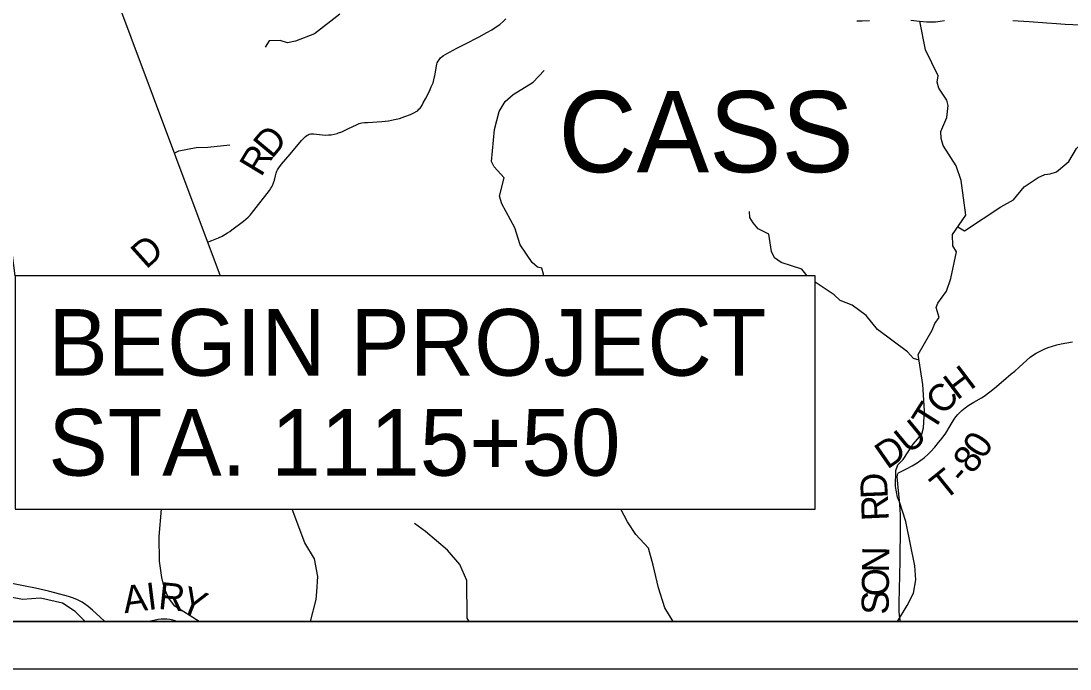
# Model space of a CAD drawing. Extents: x 0 to 34, y 0 to 22.
# Drawn here: x 26.74 to 28.944, y 14 to 15.361 of the extents above; entities that cross this region are included whole.
import ezdxf

# ---------------------------------------------------------------- set-up
doc = ezdxf.new("R2010")
doc.units = 0
for name, color, linetype in [('GM_X_Adjacent_County', 7, 'Continuous'), ('GM_X_County', 7, 'Continuous'), ('GM_X_Minor_River', 7, 'Continuous'), ('GM_X_Township', 7, 'Continuous'), ('GM_X_Township_Road', 7, 'Continuous'), ('GM_X_Township_Road_Text', 7, 'Continuous'), ('GM_X_Township_Text', 7, 'Continuous'), ('SH_Data', 7, 'Continuous'), ('SH_Text', 7, 'Continuous')]:
    doc.layers.add(name, color=color, linetype=linetype)

msp = doc.modelspace()

# ---------------------------------------------------------------- linework, layer by layer
at = {"layer": 'GM_X_Adjacent_County'}
msp.add_lwpolyline([(24.0167, 18.0693), (24.0167, 14.1), (30.8167, 14.1), (30.8167, 17.8174)], dxfattribs=at)
at = {"layer": 'GM_X_County'}
msp.add_lwpolyline([(24.0167, 18.0693), (24.0167, 14.1), (30.8167, 14.1), (30.8167, 17.8174)], dxfattribs=at)
at = {"layer": 'GM_X_Minor_River'}
for points in [[(27.4101, 15.3755), (27.3568, 15.3343), (27.3167, 15.3186), (27.2997, 15.3151), (27.2845, 15.3203), (27.2614, 15.3194), (27.2527, 15.3061)], [(28.582, 14.1), (28.6017, 14.1332), (28.6156, 14.1595), (28.62, 14.1876), (28.618, 14.2164), (28.5993, 14.3096), (28.5859, 14.3509), (28.5817, 14.3608), (28.5774, 14.3835), (28.5784, 14.4173), (28.5821, 14.4287), (28.5938, 14.4401), (28.6149, 14.4725), (28.6326, 14.4934), (28.636, 14.5063), (28.6381, 14.5424), (28.6352, 14.5974), (28.6254, 14.6603), (28.6547, 14.7117), (28.66, 14.7257), (28.6694, 14.7387), (28.6628, 14.7591), (28.6662, 14.7686), (28.6843, 14.7934), (28.694, 14.8203), (28.7059, 14.8765), (28.6982, 14.8886), (28.6974, 14.9129), (28.7249, 14.9536), (28.7154, 15.0264), (28.705, 15.0567), (28.6776, 15.0995), (28.6737, 15.1143), (28.6725, 15.1287), (28.6852, 15.1587), (28.6878, 15.1834), (28.6851, 15.1947), (28.6683, 15.2201), (28.6652, 15.233), (28.6674, 15.2463), (28.6406, 15.3004), (28.6286, 15.3606)], [(28.7082, 14.929), (28.7227, 14.9202), (28.7987, 14.9707), (28.8251, 14.9852), (28.8481, 15.013), (28.8769, 15.0325), (28.8912, 15.039), (28.9026, 15.0402), (28.9155, 15.0444), (28.9419, 15.0661), (28.9577, 15.0931), (28.9818, 15.1179), (29.0536, 15.1672), (29.0729, 15.1885), (29.0886, 15.2235), (29.0931, 15.2364), (29.1081, 15.2683), (29.1319, 15.2919), (29.1889, 15.3354), (29.1999, 15.34)], [(27.8381, 14.8261), (27.8382, 14.8297), (27.8347, 14.8418), (27.8249, 14.8444), (27.8142, 14.8538), (27.789, 14.8913), (27.7779, 14.9269), (27.75, 14.9772), (27.7457, 14.9931), (27.7554, 15.0315), (27.7345, 15.0545), (27.7287, 15.0663), (27.7352, 15.1331), (27.7445, 15.1711), (27.7573, 15.192), (27.7743, 15.2068), (27.8159, 15.2328), (27.8393, 15.2572)], [(27.0621, 15.0835), (27.0718, 15.0883), (27.1078, 15.0953), (27.1324, 15.0962), (27.1786, 15.1009)], [(28.3922, 14.8261), (28.3805, 14.8398), (28.3372, 14.8536), (28.3235, 14.8638), (28.3166, 14.8767), (28.3112, 14.9134), (28.2887, 14.9247), (28.2785, 14.9372), (28.2712, 14.9482), (28.2708, 14.9611)], [(28.6271, 14.649), (28.6152, 14.6523), (28.603, 14.6663), (28.5399, 14.713), (28.5155, 14.7429), (28.4862, 14.7644), (28.4611, 14.7738), (28.4489, 14.7862), (28.4085, 14.8128)], [(27.1144, 14.1), (27.0629, 14.1323), (27.0496, 14.1497), (27.0412, 14.169), (27.0361, 14.1921), (27.031, 14.2266), (27.0304, 14.2782), (27.0351, 14.3361)], [(27.3486, 14.1), (27.3604, 14.1461), (27.3618, 14.1624), (27.3636, 14.1943), (27.3566, 14.2311), (27.3364, 14.2651), (27.3095, 14.3361)], [(28.1104, 14.1), (28.0931, 14.1286), (28.0792, 14.1707), (28.068, 14.2184), (28.0584, 14.2541), (28.0321, 14.2828), (28.0146, 14.3092), (28.0002, 14.3361)], [(27.6815, 14.1), (27.6774, 14.1066), (27.6767, 14.1859), (27.6621, 14.2192), (27.6358, 14.2494), (27.5898, 14.2887), (27.567, 14.306)], [(26.8747, 14.1), (26.8538, 14.1207), (26.8275, 14.1381), (26.7809, 14.1485), (26.7434, 14.1461), (26.6959, 14.1553), (26.6838, 14.1587), (26.6424, 14.1718)]]:
    msp.add_lwpolyline(points, dxfattribs=at)
at = {"layer": 'GM_X_Township'}
msp.add_line((26.1244, 14.1), (30.0847, 14.1), dxfattribs=at)
at = {"layer": 'GM_X_Township_Road'}
for points in [[(27.1322, 14.8963), (27.1408, 14.8999), (27.1482, 14.9027), (27.1552, 14.906), (27.1626, 14.9095), (27.168, 14.9124), (27.1742, 14.9161), (27.1786, 14.9192), (27.1829, 14.9227), (27.2075, 14.9408), (27.2124, 14.9447), (27.217, 14.949), (27.2214, 14.9536), (27.2293, 14.9632), (27.2388, 14.9755), (27.2523, 14.9925), (27.2619, 15.0054), (27.2651, 15.0097), (27.267, 15.0126), (27.2688, 15.0158), (27.2709, 15.0211), (27.2724, 15.027), (27.2746, 15.0359), (27.2761, 15.0415), (27.2777, 15.0456), (27.2791, 15.0482), (27.2821, 15.0528), (27.2877, 15.0602), (27.3056, 15.0817), (27.3296, 15.11), (27.3337, 15.1146), (27.3381, 15.1188), (27.3405, 15.1206), (27.3431, 15.1221), (27.3458, 15.1232), (27.3487, 15.1238), (27.3517, 15.124), (27.3547, 15.1239), (27.3733, 15.1219), (27.3795, 15.1216), (27.3858, 15.1217), (27.392, 15.1223), (27.3981, 15.1234), (27.4041, 15.125), (27.4069, 15.1259), (27.4095, 15.1268), (27.4118, 15.1276), (27.4143, 15.1286), (27.4197, 15.131), (27.4281, 15.135), (27.4447, 15.1434), (27.4508, 15.1456), (27.4564, 15.1471), (27.4621, 15.1478), (27.4682, 15.1481), (27.4787, 15.1485), (27.4979, 15.1499), (27.5121, 15.1518), (27.5248, 15.154), (27.5352, 15.1563), (27.5463, 15.1603), (27.5584, 15.1651), (27.5655, 15.1684), (27.5714, 15.1717), (27.5737, 15.1733), (27.5762, 15.1757), (27.5785, 15.1783), (27.5806, 15.1809), (27.5826, 15.1843), (27.5853, 15.1893), (27.5899, 15.1975), (27.5984, 15.2141), (27.6021, 15.2226), (27.6058, 15.2315), (27.6073, 15.2374), (27.6096, 15.2464), (27.6102, 15.2494), (27.613, 15.2669), (27.6138, 15.2702), (27.6146, 15.273), (27.6163, 15.2765), (27.6183, 15.2798), (27.6216, 15.2836), (27.6248, 15.2865), (27.6279, 15.289), (27.6327, 15.2918), (27.656, 15.3038), (27.6642, 15.3083), (27.6724, 15.3127), (27.7028, 15.3282), (27.7191, 15.3368), (27.729, 15.3426), (27.7386, 15.3486), (27.746, 15.3541), (27.7537, 15.3606), (27.7589, 15.3655)], [(28.6099, 15.3631), (28.6279, 15.3607), (28.6433, 15.3594), (28.6533, 15.3594), (28.6617, 15.3595), (28.6713, 15.3606), (28.6807, 15.3621)], [(28.4959, 15.3618), (28.5072, 15.3612), (28.5228, 15.3619)], [(28.8242, 15.3621), (28.858, 15.3604), (28.8956, 15.3575), (28.916, 15.3556), (28.9341, 15.3542), (28.966, 15.3532)], [(28.582, 14.4087), (28.5825, 14.4099), (28.5832, 14.4111), (28.5841, 14.412), (28.585, 14.4128), (28.5877, 14.4144), (28.6017, 14.421), (28.6126, 14.427), (28.6232, 14.4334), (28.631, 14.4385), (28.6384, 14.4441), (28.6454, 14.4503), (28.652, 14.4569), (28.6602, 14.4662), (28.668, 14.4759), (28.6755, 14.4851), (28.6829, 14.4955), (28.6925, 14.511), (28.7007, 14.5246), (28.7043, 14.5297), (28.7081, 14.5345), (28.7123, 14.539), (28.7168, 14.5432), (28.7241, 14.5489), (28.7317, 14.5541), (28.7423, 14.5605), (28.7584, 14.5697), (28.7636, 14.573), (28.776, 14.582), (28.7856, 14.5897), (28.8043, 14.6058), (28.8208, 14.6197), (28.8279, 14.6258), (28.8371, 14.634), (28.8532, 14.6487), (28.8602, 14.6548), (28.8652, 14.6585), (28.8731, 14.6635), (28.8813, 14.6679), (28.8897, 14.6718), (28.8984, 14.6752), (28.9072, 14.6782), (28.9162, 14.6807), (28.9253, 14.6827), (28.9497, 14.6871)], [(28.588, 14.1), (28.5873, 14.1034), (28.586, 14.1126), (28.5853, 14.1218), (28.5853, 14.1373), (28.5859, 14.1684), (28.5866, 14.1963), (28.5871, 14.2273), (28.5876, 14.2521), (28.5878, 14.2738), (28.5883, 14.3109), (28.5881, 14.3233), (28.5875, 14.3357), (28.5857, 14.3542), (28.5822, 14.3882), (28.5814, 14.3974), (28.5812, 14.4027), (28.5813, 14.4048), (28.5815, 14.4067), (28.582, 14.4087)], [(26.9166, 14.1), (26.9157, 14.1007), (26.9063, 14.1087), (26.8902, 14.1234), (26.8808, 14.1315), (26.8734, 14.1371), (26.8682, 14.1405), (26.8627, 14.1434), (26.8571, 14.1459), (26.8484, 14.1492), (26.8395, 14.1521), (26.8216, 14.1572), (26.7976, 14.1634), (26.7704, 14.1696), (26.7491, 14.1742), (26.7035, 14.1832), (26.6762, 14.1888), (26.6579, 14.1921), (26.6395, 14.1947), (26.623, 14.1963)], [(27.0675, 14.1), (27.0619, 14.1017), (27.0528, 14.1038), (27.0467, 14.1048), (27.0407, 14.105), (27.0344, 14.1047), (27.0279, 14.1038), (27.0194, 14.102), (27.0088, 14.1)]]:
    msp.add_lwpolyline(points, dxfattribs=at)
at = {"layer": 'SH_Data'}
for points in [[(23.9167, 21), (30.9167, 21), (30.9167, 14), (23.9167, 14)], [(24.0167, 20.9), (30.8167, 20.9), (30.8167, 14.1), (24.0167, 14.1)]]:
    msp.add_lwpolyline(points, close=True, dxfattribs=at)
at = {"layer": 'SH_Text'}
for points in [[(26.5011, 16.5809), (27.1585, 14.8261), (26.7275, 14.8261)], [(26.7275, 14.3361), (28.4085, 14.3361), (28.4085, 14.8261), (26.7275, 14.8261)]]:
    msp.add_lwpolyline(points, close=True, dxfattribs=at)

# ---------------------------------------------------------------- texts
at = {"layer": 'GM_X_Township_Road_Text'}
for s, rotation, p in [('D', 50.2672, (27.2672, 15.0699)), ('R', 58.8937, (27.2444, 15.0318)), ('D', 41.8792, (27.0031, 14.8384)), ('H', 37.1606, (28.7067, 14.5633)), ('C', 48.4352, (28.6779, 14.5304)), ('T', 57.6853, (28.6566, 14.4964)), ('U', 39.5193, (28.6051, 14.4499)), ('D', 34.8419, (28.56, 14.4182)), ('0', 56.6928, (28.7624, 14.4384)), ('8', 53.3526, (28.7395, 14.4074)), ('T', 38.8974, (28.6799, 14.3521)), ('-', 47.8427, (28.72, 14.3855)), ('D', 92.4049, (28.5615, 14.3587)), ('R', 92.5574, (28.5636, 14.3122)), ('N', 89.1585, (28.5639, 14.2023)), ('O', 89.1731, (28.5632, 14.1523)), ('A', 7.6912, (26.9578, 14.117)), ('I', 7.0747, (27.0072, 14.1236)), ('R', 354.1038, (27.027, 14.1265)), ('Y', 338.5767, (27.0694, 14.1226)), ('S', 90.0618, (28.5632, 14.1142))]:
    msp.add_text(s, height=0.0568, rotation=rotation, dxfattribs=at).set_placement(p)
at = {"layer": 'GM_X_Township_Text'}
msp.add_text('CASS', height=0.17045, rotation=0, dxfattribs=at).set_placement((27.8692, 15.0435))
at = {"layer": 'SH_Text'}
for s, p in [('BEGIN PROJECT', (26.7975, 14.6161)), ('STA. 1115+50', (26.7975, 14.4061))]:
    msp.add_text(s, height=0.14, dxfattribs=at).set_placement(p)

doc.saveas('drawing.dxf')
